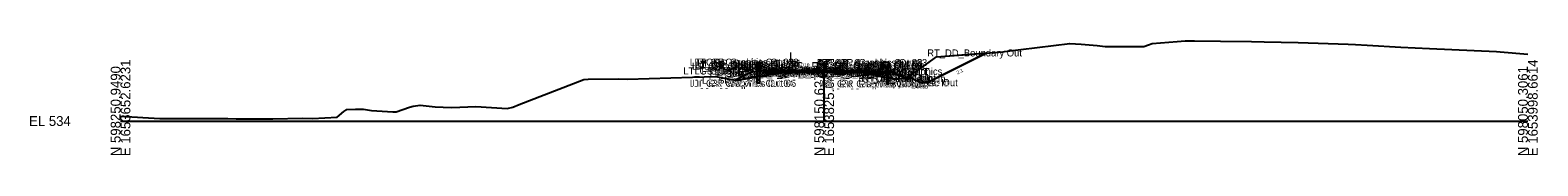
# Model space of a CAD drawing. Extents: x -26 to 403, y -10 to 6021.
# Drawn here: x -25.7 to 402.8, y 4990.3 to 5022.8 of the extents above; entities that cross this region are included whole.
import ezdxf

# ---------------------------------------------------------------- set-up
doc = ezdxf.new("R2010")
doc.units = 0
for name, color, linetype in [('Default', 7, 'Continuous'), ('Exist Cross Section Cell', 7, 'Continuous'), ('Exist XS Ground Line', 7, 'Continuous'), ('Prop CMT Ditch DDE', 7, 'Continuous'), ('Prop CMT Guardrail Graphics', 7, 'Continuous'), ('Prop CMT Pvmt Course 1', 7, 'Continuous'), ('Prop CMT Pvmt Course 1 Wedge', 7, 'Continuous'), ('Prop CMT Pvmt Course 2', 7, 'Continuous'), ('Prop CMT Pvmt Course 2 Wedge', 7, 'Continuous'), ('Prop CMT Pvmt Course 3', 7, 'Continuous'), ('Prop CMT Pvmt Course 3 Wedge', 7, 'Continuous'), ('Prop CMT Pvmt Surface', 7, 'Continuous'), ('Prop CMT Pvmt Surface Shoulder', 7, 'Continuous'), ('Prop CMT Pvmt Wedge Surface 1', 7, 'Continuous'), ('Prop CMT Pvmt Wedge Surface 2', 7, 'Continuous'), ('Prop CMT Pvmt Wedge Surface 3', 7, 'Continuous'), ('Prop CMT Shld Paved Course 1', 7, 'Continuous'), ('Prop CMT Shld Paved Course 2', 7, 'Continuous'), ('Prop CMT Shld Paved Course 3', 7, 'Continuous'), ('Prop CMT Slope Grass', 7, 'Continuous'), ('Prop CMT Subgrade Earthwork', 7, 'Continuous'), ('Prop XS Ditch Slope Text', 7, 'Continuous'), ('Prop XS Ditch Standard Text', 7, 'Continuous'), ('Prop XS Earthwork Shape', 7, 'Continuous'), ('Prop XS SE Text', 7, 'Continuous'), ('Prop XS Side Slope Text', 7, 'Continuous')]:
    doc.layers.add(name, color=color, linetype=linetype)

msp = doc.modelspace()

# ---------------------------------------------------------------- linework, layer by layer
at = {"layer": 'Exist Cross Section Cell'}
for p, q in [((200, 5000), (200, 5016.73)), ((0, 5000), (200, 5000)), ((200, 5000), (400, 5000))]:
    msp.add_line(p, q, dxfattribs=at)
at = {"layer": 'Exist XS Ground Line'}
msp.add_lwpolyline([(0, 5001.39), (11.17, 5000.72), (12.02, 5000.72), (13.38, 5000.71), (15.87, 5000.68), (30.46, 5000.67), (32.82, 5000.65), (40.73, 5000.58), (42.07, 5000.63), (42.66, 5000.58), (43.29, 5000.63), (51.69, 5000.78), (54.56, 5000.71), (61.55, 5001.05), (63.5, 5002.66), (64.34, 5003.24), (66.78, 5003.34), (69.04, 5003.38), (71.37, 5003.03), (77.37, 5002.63), (78.32, 5002.58), (82.17, 5003.97), (83.19, 5004.2), (85.2, 5004.52), (89.42, 5004.06), (94.01, 5003.85), (96.42, 5003.94), (100.95, 5004.12), (109.87, 5003.57), (111.53, 5003.96), (113.31, 5004.66), (131.69, 5011.79), (132.87, 5011.9), (141.54, 5011.99), (144.11, 5011.92), (150.23, 5012.06), (162.61, 5012.47), (169.22, 5012.61), (173.62, 5011.8), (174.97, 5011.57), (176.48, 5011.79), (178.73, 5012.2), (182.99, 5012.95), (188, 5013.7), (190.83, 5013.76), (200, 5013.98), (200.04, 5013.98), (205.85, 5013.83), (211.89, 5013.66), (215.5, 5012.88), (217.76, 5012.24), (219.87, 5011.9), (220.11, 5011.89), (220.34, 5011.91), (222.81, 5012.16), (223.41, 5012.43), (223.93, 5012.71), (225.22, 5013.4), (229.14, 5016.24), (230.92, 5017.45), (231.88, 5018.26), (249.66, 5019.61), (250.78, 5019.69), (250.84, 5019.7), (251.26, 5019.75), (269.77, 5022.07), (273.02, 5021.81), (276.46, 5021.53), (277.55, 5021.42), (279.82, 5021.18), (284.53, 5021.14), (290.84, 5021.17), (292.19, 5021.65), (293.21, 5022.01), (300.37, 5022.61), (302.62, 5022.77), (305.29, 5022.76), (312.62, 5022.65), (321.47, 5022.56), (325.07, 5022.51), (334.73, 5022.36), (348.91, 5021.82), (351.03, 5021.77), (354.34, 5021.55), (363.9, 5021.03), (372.05, 5020.62), (391.06, 5019.71), (392.09, 5019.64), (400, 5019.03)], dxfattribs=at)
at = {"layer": 'Prop CMT Ditch DDE'}
msp.add_lwpolyline([(223, 5012.25), (225, 5012.08), (227.37, 5010.9), (229.37, 5010.9), (246.27, 5019.35)], dxfattribs=at)
at = {"layer": 'Prop CMT Guardrail Graphics'}
for points in [[(180.9, 5010.72), (180.9, 5016.72)], [(180.9, 5016.72), (182.23, 5016.72), (182.5, 5016.43)], [(182.5, 5015.84), (182.23, 5015.55), (181.57, 5015.55)], [(181.57, 5015.55), (181.57, 5010.72)], [(182.5, 5016.43), (182.23, 5016.13)], [(182.23, 5016.13), (182.5, 5015.84)], [(218.39, 5016.6), (217.05, 5016.6), (216.78, 5016.31)], [(216.78, 5016.31), (217.05, 5016.02)], [(217.05, 5016.02), (216.78, 5015.72)], [(216.78, 5015.72), (217.05, 5015.43), (217.72, 5015.43)], [(217.72, 5015.43), (217.72, 5010.6)], [(218.39, 5010.6), (218.39, 5016.6)], [(181.57, 5010.72), (180.9, 5010.72)], [(217.72, 5010.6), (218.39, 5010.6)]]:
    msp.add_lwpolyline(points, dxfattribs=at)
at = {"layer": 'Prop CMT Pvmt Course 1'}
for points in [[(200, 5014.48), (188, 5014.36)], [(188, 5014.36), (188, 5014.15), (188, 5014.15), (188, 5014.15)], [(188, 5014.15), (200, 5014.27)], [(200, 5014.27), (200, 5014.48)], [(200, 5014.48), (212, 5014.24)], [(200, 5014.27), (200, 5014.48)], [(200, 5014.27), (200, 5014.27), (200, 5014.27)], [(211.89, 5014.04), (200, 5014.27)], [(200, 5014.27), (200, 5014.27), (200, 5014.27)], [(212, 5014.03), (211.89, 5014.04)], [(211.89, 5014.04), (211.89, 5014.04)], [(212, 5014.24), (212, 5014.03)]]:
    msp.add_lwpolyline(points, dxfattribs=at)
at = {"layer": 'Prop CMT Pvmt Course 1 Wedge'}
for points in [[(188, 5014.15), (190.83, 5014.18), (200, 5014.27)], [(200, 5014.15), (190.83, 5014.06), (188, 5014.03)], [(188, 5014.03), (188, 5014.15)], [(200, 5014.27), (200, 5014.15)], [(200, 5014.27), (200.04, 5014.27), (205.85, 5014.16), (211.89, 5014.04)], [(200, 5014.15), (200, 5014.27)], [(211.89, 5013.91), (205.85, 5014.03), (200.04, 5014.15), (200, 5014.15)], [(211.89, 5014.04), (211.89, 5013.91)]]:
    msp.add_lwpolyline(points, dxfattribs=at)
at = {"layer": 'Prop CMT Pvmt Course 2'}
for points in [[(188, 5013.95), (188, 5013.95), (188, 5014.15), (188, 5014.15)], [(188, 5014.15), (188, 5013.95)], [(211.89, 5013.83), (211.89, 5014.04)], [(211.89, 5014.04), (212, 5014.03)], [(212, 5014.03), (212, 5013.83)], [(212, 5013.83), (211.89, 5013.83)]]:
    msp.add_lwpolyline(points, dxfattribs=at)
at = {"layer": 'Prop CMT Pvmt Course 2 Wedge'}
for points in [[(188, 5014.15), (190.83, 5014.18), (200, 5014.27)], [(188, 5013.95), (188, 5014.15)], [(200, 5014.07), (190.83, 5013.97), (188, 5013.95)], [(200, 5014.27), (200, 5014.07)], [(200, 5014.27), (200.04, 5014.27), (205.85, 5014.16), (211.89, 5014.04)], [(200, 5014.07), (200, 5014.27)], [(211.89, 5013.83), (205.85, 5013.95), (200.04, 5014.06), (200, 5014.07)], [(211.89, 5014.04), (211.89, 5013.83)]]:
    msp.add_lwpolyline(points, dxfattribs=at)
at = {"layer": 'Prop CMT Pvmt Course 3'}
for points in [[(188, 5013.95), (188, 5013.95), (188, 5013.61), (188, 5013.61)], [(188, 5013.61), (188, 5013.95)], [(211.89, 5013.83), (212, 5013.83)], [(211.89, 5013.49), (211.89, 5013.83)], [(212, 5013.49), (211.89, 5013.49)], [(212, 5013.83), (212, 5013.49)]]:
    msp.add_lwpolyline(points, dxfattribs=at)
at = {"layer": 'Prop CMT Pvmt Course 3 Wedge'}
for points in [[(188, 5013.95), (190.83, 5013.97), (200, 5014.07)], [(200, 5013.98), (190.83, 5013.76), (188, 5013.7)], [(188, 5013.7), (188, 5013.95)], [(200, 5014.07), (200, 5013.98)], [(200, 5014.07), (200.04, 5014.06), (205.85, 5013.95), (211.89, 5013.83)], [(200, 5013.98), (200, 5014.07)], [(211.89, 5013.66), (205.85, 5013.83), (200.04, 5013.98), (200, 5013.98)], [(211.89, 5013.83), (211.89, 5013.66)]]:
    msp.add_lwpolyline(points, dxfattribs=at)
at = {"layer": 'Prop CMT Pvmt Surface'}
for points in [[(200, 5014.48), (188, 5014.36)], [(200, 5014.48), (212, 5014.24)]]:
    msp.add_lwpolyline(points, dxfattribs=at)
at = {"layer": 'Prop CMT Pvmt Surface Shoulder'}
for points in [[(188, 5014.36), (184, 5014.32)], [(212, 5014.24), (216, 5014.16)]]:
    msp.add_lwpolyline(points, dxfattribs=at)
at = {"layer": 'Prop CMT Pvmt Wedge Surface 1'}
for points in [[(188, 5014.15), (188, 5014.36)], [(200, 5014.27), (188, 5014.15)], [(188, 5014.15), (188, 5014.15), (188, 5014.15)], [(200, 5014.48), (200, 5014.27), (200, 5014.27), (200, 5014.27)], [(200, 5014.48), (200, 5014.27), (200, 5014.27), (200, 5014.27)], [(200, 5014.27), (211.89, 5014.04)], [(211.89, 5014.04), (211.89, 5014.04)], [(211.89, 5014.04), (212, 5014.03)], [(212, 5014.03), (212, 5014.24)]]:
    msp.add_lwpolyline(points, dxfattribs=at)
at = {"layer": 'Prop CMT Pvmt Wedge Surface 2'}
for points in [[(188, 5014.15), (188, 5014.36)], [(200, 5014.27), (188, 5014.15)], [(200, 5014.48), (200, 5014.27)], [(200, 5014.48), (200, 5014.27)], [(200, 5014.27), (212, 5014.03)], [(212, 5014.03), (212, 5014.24)]]:
    msp.add_lwpolyline(points, dxfattribs=at)
at = {"layer": 'Prop CMT Pvmt Wedge Surface 3'}
for points in [[(188, 5013.95), (188, 5014.36)], [(200, 5014.07), (188, 5013.95)], [(200, 5014.48), (200, 5014.07)], [(200, 5014.48), (200, 5014.07)], [(200, 5014.07), (212, 5013.83)], [(212, 5013.83), (212, 5014.24)]]:
    msp.add_lwpolyline(points, dxfattribs=at)
at = {"layer": 'Prop CMT Shld Paved Course 1'}
for points in [[(188, 5014.36), (184, 5014.32), (183.79, 5014.11)], [(183.79, 5014.11), (188, 5014.15)], [(188, 5014.15), (188, 5014.36)], [(212, 5014.24), (216, 5014.16), (216.21, 5013.95)], [(212, 5014.03), (212, 5014.24)], [(216.21, 5013.95), (212, 5014.03)]]:
    msp.add_lwpolyline(points, dxfattribs=at)
at = {"layer": 'Prop CMT Shld Paved Course 2'}
for points in [[(188, 5014.15), (183.79, 5014.11), (183.58, 5013.9)], [(183.58, 5013.9), (188, 5013.95)], [(188, 5013.95), (188, 5014.15)], [(212, 5014.03), (216.21, 5013.95), (216.43, 5013.74)], [(212, 5013.83), (212, 5014.03)], [(216.43, 5013.74), (212, 5013.83)]]:
    msp.add_lwpolyline(points, dxfattribs=at)
at = {"layer": 'Prop CMT Shld Paved Course 3'}
for points in [[(188, 5013.95), (183.58, 5013.9), (183.58, 5013.9), (183.24, 5013.56)], [(188, 5013.61), (188, 5013.95)], [(183.24, 5013.56), (188, 5013.61)], [(212, 5013.83), (216.43, 5013.74), (216.43, 5013.74), (216.77, 5013.4)], [(212, 5013.49), (212, 5013.83)], [(216.77, 5013.4), (212, 5013.49)]]:
    msp.add_lwpolyline(points, dxfattribs=at)
at = {"layer": 'Prop CMT Slope Grass'}
for points in [[(179.5, 5014.01), (174.72, 5011.61)], [(182.5, 5014.22), (179.5, 5014.01)], [(184, 5014.32), (182.5, 5014.22)], [(216, 5014.16), (216.78, 5014.1)], [(216.78, 5014.1), (219.78, 5013.86)], [(219.78, 5013.86), (223, 5012.25)]]:
    msp.add_lwpolyline(points, dxfattribs=at)
at = {"layer": 'Prop CMT Subgrade Earthwork'}
for points in [[(183.24, 5013.56), (182.58, 5014.22)], [(216.77, 5013.4), (217.42, 5014.05)], [(188, 5013.61), (183.24, 5013.56)], [(188, 5013.61), (188.02, 5013.7)], [(188, 5013.61), (188, 5013.61)], [(211.89, 5013.49), (211.88, 5013.66)], [(211.89, 5013.49), (212, 5013.49)], [(212, 5013.49), (216.77, 5013.4)]]:
    msp.add_lwpolyline(points, dxfattribs=at)
at = {"layer": 'Prop XS Earthwork Shape'}
for points in [[(223, 5012.25), (223.41, 5012.43), (223.93, 5012.71), (225.22, 5013.4), (229.14, 5016.24), (230.92, 5017.45), (231.88, 5018.26), (246.27, 5019.35), (229.37, 5010.9), (227.37, 5010.9), (225, 5012.08)], [(187.37, 5013.61), (183.24, 5013.56), (182.58, 5014.22), (182.5, 5014.22), (179.5, 5014.01), (174.72, 5011.61), (174.97, 5011.57), (176.48, 5011.79), (178.73, 5012.2), (182.99, 5012.95)], [(187.37, 5013.61), (183.24, 5013.56), (182.58, 5014.22), (184, 5014.32), (188, 5014.36), (188, 5014.15), (200, 5014.27), (211.89, 5014.04), (212, 5014.03), (212, 5014.24), (216, 5014.16), (216.78, 5014.1), (217.42, 5014.05), (216.77, 5013.4), (212.72, 5013.48), (211.89, 5013.66), (211.88, 5013.66), (205.85, 5013.83), (200.04, 5013.98), (200, 5013.98), (190.83, 5013.76), (188.02, 5013.7), (188, 5013.7)], [(219.78, 5013.86), (223, 5012.25), (222.81, 5012.16), (220.34, 5011.91), (220.11, 5011.89), (219.87, 5011.9), (217.76, 5012.24), (215.5, 5012.88), (212.72, 5013.48), (216.77, 5013.4), (217.42, 5014.05)], [(188, 5013.61), (188.02, 5013.7), (188, 5013.7), (187.37, 5013.61)], [(211.89, 5013.49), (211.88, 5013.66), (211.89, 5013.66), (212.72, 5013.48), (212, 5013.49)]]:
    msp.add_lwpolyline(points, close=True, dxfattribs=at)

# ---------------------------------------------------------------- texts
at = {"layer": 'Default'}
for s, height, p in [('RT_DD_Boundary Out', 2, (229.29, 5018.35)), ('LT_GS_OS_GR_Face_Graphics', 2, (159.96, 5013.22)), ('LT_GR_Graphics Out 03', 2, (161.8, 5015.72)), ('LT_GR_Graphics Out 06', 2, (162.42, 5014.55)), ('LT_GR_Graphics Out 02', 2, (163.13, 5015.72)), ('LT_GR_Graphics Out 09', 2, (163.13, 5015.13)), ('LT_GR_Graphics Out 07', 2, (163.13, 5014.55)), ('LT_Sub_Trench_Out_DLT', 2, (163.15, 5013.22)), ('LT_GR_Graphics Out 08', 2, (163.4, 5014.84)), ('LT_GR_Graphics Out 01', 2, (163.97, 5015.43)), ('LT_Sub_Trench_Out', 2, (167.45, 5012.56)), ('LT_GS_OS_CTL', 2, (168.87, 5013.01)), ('LT_PS3_Shelf_Out', 2, (169.56, 5012.9)), ('LT_PV_Sub_Tie_Out', 2, (172.96, 5012.7)), ('LT_PS3_OEOP', 2, (173.82, 5012.9)), ('LT_PS2_OEOP', 2, (174.03, 5013.11)), ('LT_PS1_OEOP', 2, (174.8, 5013.32)), ('LT_PV_OEEOP_EG', 2, (175.54, 5012.7)), ('LT_Sub_OEEOP', 2, (177.21, 5012.61)), ('LT_PV2_OEEOP', 2, (177.31, 5013.15)), ('LT_PV3_OEEOP', 2, (177.31, 5012.95)), ('LT_PV1_OEEOP', 2, (177.87, 5013.15)), ('LT_Sub_OEOT', 2, (178.08, 5012.61)), ('LT_PV2_OEOT', 2, (178.17, 5013.15)), ('LT_PV3_OEOT', 2, (178.17, 5012.95)), ('LT_PV1_OEOT', 2, (178.74, 5013.36)), ('LT_PV_EG_TestPt', 2, (180.41, 5012.84)), ('RT_PV_IEEOP_EG', 2, (188.14, 5012.98)), ('LT_PV_IEEOP_EG', 2, (188.19, 5012.98)), ('RT_Seek SS Fill O', 2, (189.44, 5013.48)), ('RT_PV2_IEEOP', 2, (189.91, 5013.27)), ('RT_PV3_IEEOP', 2, (189.91, 5013.07)), ('LT_PV2_IEEOP', 2, (189.95, 5013.27)), ('LT_PV3_IEEOP', 2, (189.95, 5013.07)), ('RT_PV1_IEEOP', 2, (190.47, 5013.27)), ('LT_PV1_IEEOP', 2, (190.52, 5013.27)), ('RT_PV_EG_TestPt', 2, (192.31, 5012.83)), ('PV2_PGL', 2, (193.91, 5013.27)), ('PV3_PGL', 2, (193.91, 5013.07)), ('RT_GS_OS_GR_Face_Graphics', 2, (194.19, 5013.1)), ('PV1_PGL', 2, (194.47, 5013.48)), ('RT_PV_Sub_Tie_Out', 2, (196.78, 5012.66)), ('RT_GR_Graphics Out 08', 2, (197.63, 5014.72)), ('RT_GR_Graphics Out 02', 2, (197.9, 5015.6)), ('RT_GR_Graphics Out 09', 2, (197.9, 5015.02)), ('RT_GR_Graphics Out 07', 2, (197.9, 5014.43)), ('RT_Sub_Trench_Out_DLT', 2, (197.94, 5013.05)), ('RT_GR_Graphics Out 01', 2, (198.2, 5015.31)), ('RT_GR_Graphics Out 06', 2, (198.52, 5014.43)), ('RT_GR_Graphics Out 03', 2, (199.24, 5015.6)), ('RT_PV_OEEOP_EG', 2, (199.39, 5012.66)), ('RT_Sub_Trench_Out', 2, (200.92, 5012.4)), ('RT_Sub_OEEOP', 2, (201.06, 5012.49)), ('RT_PV2_OEEOP', 2, (201.15, 5013.04)), ('RT_PV3_OEEOP', 2, (201.15, 5012.83)), ('RT_PV1_OEEOP', 2, (201.72, 5013.04)), ('RT_Sub_OEOT', 2, (202.03, 5012.49)), ('RT_PV2_OEOT', 2, (202.13, 5013.03)), ('RT_PV3_OEOT', 2, (202.13, 5012.83)), ('RT_PS3_Shelf_Out', 2, (202.36, 5012.74)), ('RT_PV1_OEOT', 2, (202.69, 5013.24)), ('RT_PS2_OEOP', 2, (206.4, 5012.95)), ('RT_PS3_OEOP', 2, (206.61, 5012.74)), ('RT_PS1_OEOP', 2, (206.76, 5013.16)), ('RT_GS_OS_CTL', 2, (209.1, 5012.86)), ('LT_GR_Graphics Out 04', 2, (161.8, 5009.72)), ('LT_GR_Graphics Out 05', 2, (162.46, 5009.72)), ('LT_Slope_Fill', 2, (165.24, 5010.61)), ('RT_GR_Graphics Out 05', 2, (198.57, 5009.6)), ('RT_GR_Graphics Out 04', 2, (199.24, 5009.6)), ('RT_DD_Boundary In', 2, (209.65, 5011.08)), ('RT_SS_Fill_Point', 2, (210.64, 5011.25)), ('RT_Slope_Fill', 2, (213.48, 5011.25)), ('RT_DD_Base In', 2, (216.03, 5009.9)), ('RT_DD_Base Out', 2, (216.41, 5009.9)), ('-', 0.0001, (0, 5000))]:
    msp.add_text(s, height=height, dxfattribs=at).set_placement(p)
at = {"layer": 'Exist Cross Section Cell'}
for s, p in [('L', (190, 5016.73)), ('16+50.00 / 1', (190, 5013.93)), ('EL 534', (-26, 4998.6))]:
    msp.add_text(s, height=2.8, dxfattribs=at).set_placement(p)
for s, p in [('N 598250.9490', (0, 4990)), ('E 1653652.6231', (2.8, 4990)), ('N 598150.6275', (200, 4990)), ('E 1653825.6422', (202.8, 4990)), ('N 598050.3061', (400, 4990)), ('E 1653998.6614', (402.8, 4990))]:
    msp.add_text(s, height=2.8, rotation=90, dxfattribs=at).set_placement(p)
at = {"layer": 'Prop XS Ditch Slope Text'}
for rotation, p in [(26.5651, (237.89, 5013.21)), (333.4349, (224.69, 5010.28))]:
    msp.add_text('2:1', height=1, rotation=rotation, dxfattribs=at).set_placement(p)
at = {"layer": 'Prop XS Ditch Standard Text'}
msp.add_text('544.90', height=1, dxfattribs=at).set_placement((225.22, 5009.15))
at = {"layer": 'Prop XS SE Text'}
for s, rotation, p in [('0.010', 0.5729, (192.36, 5015.41)), ('0.020', 358.8542, (204.27, 5015.4))]:
    msp.add_text(s, height=1, rotation=rotation, dxfattribs=at).set_placement(p)
at = {"layer": 'Prop XS Side Slope Text'}
for rotation, p in [(26.5651, (176.07, 5013.13)), (333.4349, (221.02, 5014.08))]:
    msp.add_text('2:1', height=1, rotation=rotation, dxfattribs=at).set_placement(p)

doc.saveas('drawing.dxf')
